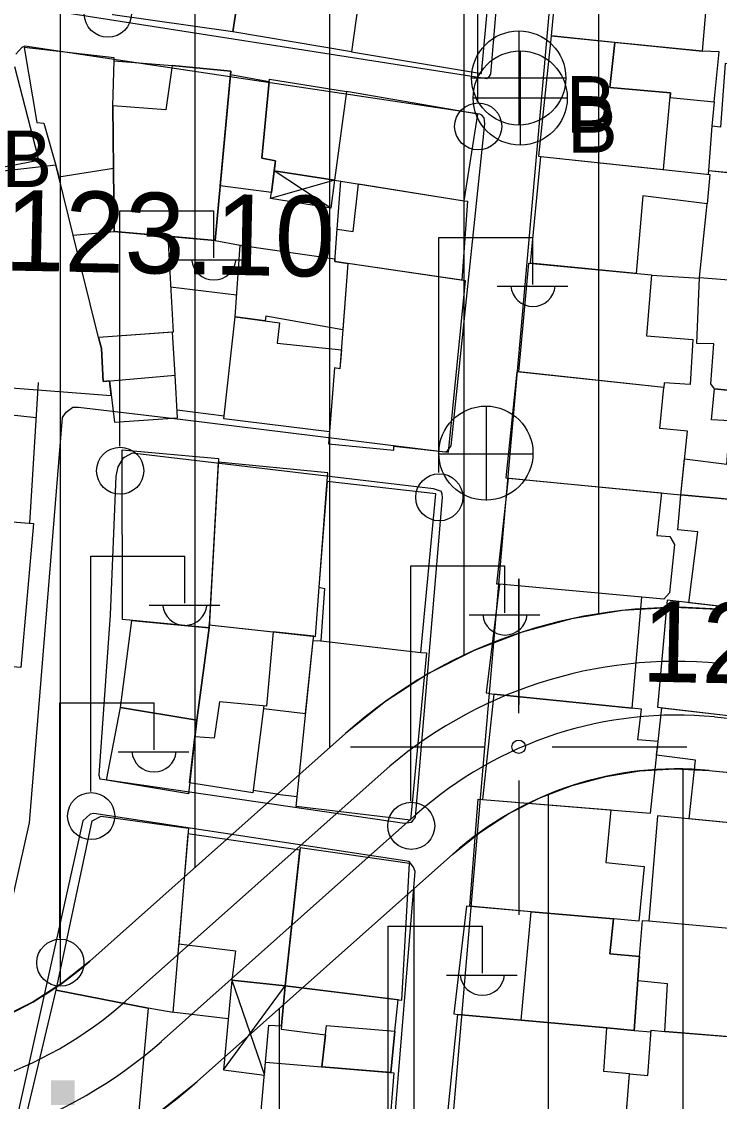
# Model space of a CAD drawing. Extents: x 417997 to 421451, y 4451742 to 4455216.
# Drawn here: x 419463 to 419514.9, y 4452473.6 to 4452553.9 of the extents above; entities that cross this region are included whole.
import ezdxf

# ---------------------------------------------------------------- set-up
doc = ezdxf.new("R2010")
doc.units = 0
for name, color, linetype in [('ADAKENARI', 7, 'Continuous'), ('B_Kapi', 7, 'Continuous'), ('B_Mesken', 7, 'Continuous'), ('B_Sundurma', 7, 'Continuous'), ('B_Teras', 7, 'Continuous'), ('KALDIRIM', 7, 'Continuous'), ('P_Grid', 7, 'Continuous'), ('PAFTALAMA', 7, 'Continuous'), ('PL_KON_MEV_350', 7, 'Continuous'), ('S_Elektrik_Diregi', 7, 'Continuous'), ('S_Rogar_Kapagi', 7, 'Continuous'), ('S_Rogar_Kapagi_Buski', 7, 'Continuous'), ('Sinir_Duvar_tek_tarafa_ait', 7, 'Continuous'), ('TR_ORTAYOGUNKONUT', 7, 'Continuous'), ('Y_Bucak_Koy', 7, 'Continuous'), ('Y_Kot_Noktasi', 7, 'Continuous'), ('Y_Yol_Kotu', 7, 'Continuous'), ('Yol_Sose', 7, 'Continuous')]:
    doc.layers.add(name, color=color, linetype=linetype)

msp = doc.modelspace()

# ---------------------------------------------------------------- linework, layer by layer
at = {"layer": 'ADAKENARI'}
for p, q in [((419487.115, 4452500.985), (419468.114, 4452484.062)), ((419487.115, 4452500.985), (419468.114, 4452484.062)), ((419514.164, 4452498.235), (419572.575, 4452492.506)), ((419514.164, 4452498.235), (419572.575, 4452492.506)), ((419476.095, 4452475.101), (419495.096, 4452492.024)), ((419476.095, 4452475.101), (419495.096, 4452492.024))]:
    msp.add_line(p, q, dxfattribs=at)
for centre, radius, start, end in [((419511.724, 4452473.355), 37, 84.39749, 131.68944), ((419511.724, 4452473.355), 37, 84.39749, 131.68944), ((419511.724, 4452473.355), 25, 84.39749, 131.68944), ((419511.724, 4452473.355), 25, 84.39749, 131.68944), ((419451.487, 4452502.731), 25, 263.99099, 311.68944), ((419451.487, 4452502.731), 25, 263.99099, 311.68944), ((419451.487, 4452502.731), 37, 263.99099, 311.68944), ((419451.487, 4452502.731), 37, 263.99099, 311.68944)]:
    msp.add_arc(centre, radius, start, end, dxfattribs=at)
at = {"layer": 'B_Kapi'}
msp.add_lwpolyline([(419482.052, 4452496.488), (419483.526, 4452496.293)], dxfattribs=at)
at = {"layer": 'B_Mesken'}
for points in [[(419487.577, 4452551.697), (419478.757, 4452553.178), (419480.1, 4452562.035), (419483.31, 4452561.933), (419486.927, 4452561.808), (419487.318, 4452565.246), (419489.412, 4452564.839)], [(419489.412, 4452564.839), (419487.577, 4452551.697), (419497.235, 4452550.077), (419498.082, 4452559.256), (419494.228, 4452559.813), (419494.672, 4452563.733)], [(419478.757, 4452553.178), (419469.823, 4452554.432), (419471.167, 4452563.02), (419476.451, 4452562.322), (419476.543, 4452562.911), (419480.136, 4452562.292), (419480.1, 4452562.035)], [(419502.405, 4452552.868), (419513.663, 4452551.734), (419514.367, 4452559.818), (419503.293, 4452562.166)], [(419510.764, 4452542.939), (419511.283, 4452548.64), (419506.782, 4452549.042), (419507.142, 4452552.391), (419502.405, 4452552.868), (419501.469, 4452543.933), (419501.651, 4452543.909)], [(419469.936, 4452551.01), (419469.937, 4452551.236), (419463.236, 4452552.007), (419464.169, 4452546.436), (419464.712, 4452546.389), (419465.573, 4452543.34), (419465.806, 4452542.4), (419469.875, 4452543.046), (419469.834, 4452547.683)], [(419511.251, 4452548.287), (419514.521, 4452547.981), (419514.896, 4452551.679), (419513.663, 4452551.734), (419507.142, 4452552.391), (419506.782, 4452549.042), (419511.283, 4452548.64)], [(419469.834, 4452547.683), (419469.936, 4452551.01), (419474.25, 4452550.664), (419478.609, 4452550.24), (419477.432, 4452537.646), (419473.92, 4452537.966), (419469.917, 4452538.331), (419469.875, 4452543.046)], [(419526.655, 4452541.789), (419527.383, 4452549.635), (419519.27, 4452550.389), (419515.355, 4452550.832), (419515, 4452546.083), (419514.366, 4452546.153), (419514.106, 4452542.852), (419515.768, 4452542.7), (419519.526, 4452542.357), (419521.054, 4452542.217)], [(419478.587, 4452550.004), (419481.459, 4452549.474), (419480.897, 4452543.779), (419481.914, 4452543.572), (419481.635, 4452541.222), (419477.814, 4452541.728)], [(419481.459, 4452549.474), (419481.482, 4452549.655), (419487.202, 4452548.73), (419486.298, 4452542.155), (419481.827, 4452542.838), (419481.914, 4452543.572), (419480.897, 4452543.779)], [(419486.298, 4452542.155), (419495.952, 4452540.606), (419496.969, 4452547.046), (419487.202, 4452548.73)], [(419500.874, 4452535.959), (419501.651, 4452543.909), (419514.221, 4452542.57), (419514.009, 4452540.39), (419509.236, 4452540.974), (419508.729, 4452535.209)], [(419459.73, 4452542.581), (419457.749, 4452527.056), (419469.704, 4452526.116), (419469.571, 4452527.208), (419469.114, 4452527.167), (419468.979, 4452529.618), (419468.773, 4452530.451), (419466.884, 4452538.059), (419465.806, 4452542.4), (419465.593, 4452543.262)], [(419466.884, 4452538.059), (419465.806, 4452542.4), (419469.875, 4452543.046), (419469.917, 4452538.331), (419473.92, 4452537.966), (419474.304, 4452530.836), (419468.773, 4452530.451)], [(419495.952, 4452540.606), (419496.201, 4452540.583), (419495.785, 4452534.708), (419487.303, 4452535.942), (419486.331, 4452536.104), (419486.498, 4452538.5), (419487.696, 4452538.315), (419488.086, 4452541.868)], [(419478.919, 4452531.972), (419479.299, 4452537.306), (419486.344, 4452536.287), (419486.331, 4452536.104), (419487.303, 4452535.942), (419486.931, 4452531.021), (419481.211, 4452532.036), (419481.163, 4452531.672)], [(419487.303, 4452535.942), (419486.712, 4452528.123), (419486.305, 4452528.192), (419485.856, 4452522.542), (419490.719, 4452522.05), (419490.72, 4452522.366), (419494.79, 4452521.922), (419496.054, 4452534.668)], [(419500.001, 4452527.881), (419500.754, 4452535.971), (419509.869, 4452535.1), (419509.514, 4452530.568), (419512.954, 4452530.292), (419512.739, 4452526.939), (419510.811, 4452527.081), (419510.784, 4452526.727)], [(419525.903, 4452533.648), (419525.196, 4452525.538), (419514.563, 4452526.618), (419514.292, 4452527.004), (419514.506, 4452529.972), (419513.236, 4452529.999), (419513.434, 4452534.893), (419515.313, 4452534.749), (419519.137, 4452534.396)], [(419485.927, 4452523.425), (419478.08, 4452524.402), (419478.919, 4452531.972), (419482.221, 4452531.531), (419482.035, 4452530.017), (419486.819, 4452529.536), (419486.712, 4452528.123), (419486.305, 4452528.192)], [(419474.46, 4452527.646), (419474.263, 4452530.833), (419468.773, 4452530.451), (419468.979, 4452529.618), (419469.114, 4452527.167), (419469.571, 4452527.208), (419469.945, 4452524.151), (419474.634, 4452524.474)], [(419499.037, 4452519.995), (419512.047, 4452518.739), (419512.538, 4452523.464), (419510.502, 4452523.675), (419510.784, 4452526.727), (419499.856, 4452527.897)], [(419525.196, 4452525.538), (419525.468, 4452525.537), (419524.725, 4452517.583), (419512.047, 4452518.739), (419512.326, 4452521.429), (419515.477, 4452521.01), (419515.715, 4452524.249), (419514.332, 4452524.322), (419514.563, 4452526.618)], [(419477.679, 4452521.436), (419476.981, 4452508.848), (419470.559, 4452509.459), (419470.533, 4452522.094)], [(419476.994, 4452509.077), (419484.907, 4452508.212), (419485.172, 4452511.862), (419485.722, 4452519.14), (419485.817, 4452520.383), (419477.664, 4452521.178)], [(419485.301, 4452507.869), (419492.717, 4452507.006), (419493.842, 4452518.824), (419485.77, 4452519.734), (419485.134, 4452511.871), (419485.563, 4452511.779)], [(419498.572, 4452512.086), (419498.369, 4452512.087), (419499.25, 4452519.974), (419510.609, 4452518.878), (419510.259, 4452515.713), (419511.232, 4452515.642), (419511.592, 4452515.053), (419511.218, 4452511.458), (419510.786, 4452510.985), (419509.161, 4452511.121)], [(419512.654, 4452510.71), (419513.328, 4452515.976), (419511.835, 4452516.14), (419512.047, 4452518.739), (419524.942, 4452517.563), (419524.165, 4452509.391)], [(419451.216, 4452504.421), (419452.483, 4452517.505), (419463.944, 4452516.603), (419462.979, 4452505.896), (419459.65, 4452506.18), (419459.412, 4452502.874), (419455.879, 4452503.204), (419455.904, 4452504.065)], [(419508.432, 4452502.869), (419509.161, 4452511.121), (419498.572, 4452512.086), (419497.572, 4452504.016), (419498.15, 4452503.924)], [(419510.317, 4452502.943), (419523.36, 4452501.419), (419524.165, 4452509.391), (419511.041, 4452510.895)], [(419476.981, 4452508.848), (419476.076, 4452501.98), (419470.402, 4452502.927), (419471.236, 4452509.395)], [(419481.055, 4452503.04), (419480.242, 4452496.578), (419475.541, 4452497.313), (419475.933, 4452500.735), (419476.076, 4452501.98), (419476.981, 4452508.848), (419476.994, 4452509.077), (419481.75, 4452508.557), (419481.257, 4452503.021)], [(419481.032, 4452502.852), (419484.158, 4452502.484), (419484.713, 4452507.916), (419484.784, 4452508.226), (419481.75, 4452508.557), (419481.257, 4452503.021), (419481.055, 4452503.04)], [(419492.717, 4452507.006), (419493.147, 4452506.982), (419491.952, 4452494.532), (419483.451, 4452495.557), (419484.713, 4452507.916), (419485.301, 4452507.869)], [(419497.309, 4452496.08), (419509.799, 4452495.062), (419510.36, 4452500.397), (419508.866, 4452500.515), (419509.123, 4452502.798), (419498.15, 4452503.924)], [(419469.366, 4452497.506), (419470.402, 4452502.927), (419476.076, 4452501.98), (419475.447, 4452496.49)], [(419522.878, 4452501.476), (419522.038, 4452493.729), (419512.667, 4452494.639), (419513.135, 4452499.009), (419510.253, 4452499.385), (419510.36, 4452500.397), (419510.648, 4452502.904)], [(419496.367, 4452488.134), (419496.992, 4452496.104), (419497.309, 4452496.08), (419506.843, 4452495.303), (419506.468, 4452491.392), (419509.318, 4452491.087), (419508.943, 4452487.04), (419507.037, 4452487.212), (419500.928, 4452487.732)], [(419465.629, 4452481.899), (419468.297, 4452494.493), (419468.955, 4452494.852), (419475.45, 4452493.946), (419474.295, 4452480.238), (419472.452, 4452480.557)], [(419509.685, 4452487.055), (419521.334, 4452485.996), (419522.038, 4452493.729), (419510.31, 4452494.868)], [(419483.725, 4452492.305), (419475.414, 4452493.516), (419474.726, 4452485.35), (419478.958, 4452484.814), (419478.679, 4452482.643), (419482.646, 4452482.217)], [(419483.744, 4452492.485), (419482.646, 4452482.217), (419491.314, 4452481.144), (419491.891, 4452491.324)], [(419500.928, 4452487.732), (419496.109, 4452488.157), (419495.177, 4452480.132), (419495.44, 4452480.079), (419500.177, 4452479.661), (419506.554, 4452479.1), (419508.594, 4452478.907), (419508.594, 4452478.907), (419508.974, 4452484.401), (419506.78, 4452484.59), (419507.037, 4452487.212)], [(419521.334, 4452485.996), (419521.877, 4452485.949), (419521.149, 4452477.991), (419510.854, 4452478.82), (419511.069, 4452482.37), (419508.849, 4452482.598), (419508.974, 4452484.401), (419509.209, 4452487.069), (419509.685, 4452487.055)], [(419462.653, 4452469.381), (419465.629, 4452481.899), (419472.452, 4452480.557), (419471.333, 4452468.292)], [(419490.784, 4452478.857), (419491.035, 4452481.178), (419482.646, 4452482.217), (419482.341, 4452479.005), (419485.635, 4452478.587), (419485.364, 4452476.207), (419490.498, 4452475.779)], [(419494.656, 4452472.243), (419507.843, 4452470.678), (419508.239, 4452475.683), (419506.323, 4452475.85), (419506.554, 4452479.1), (419495.44, 4452480.079)], [(419520.78, 4452478.02), (419520.634, 4452474.742), (419520.362, 4452474.652), (419519.896, 4452470.004), (419508.848, 4452470.815), (419507.864, 4452470.941), (419508.239, 4452475.683), (419509.596, 4452475.542), (419509.857, 4452478.934), (419510.854, 4452478.82)], [(419480.333, 4452467.101), (419481.183, 4452476.554), (419490.722, 4452475.761), (419489.972, 4452466.427)]]:
    msp.add_lwpolyline(points, close=True, dxfattribs=at)
at = {"layer": 'B_Sundurma'}
for p, q in [((419486.298, 4452542.155), (419481.543, 4452540.77)), ((419486.042, 4452540.053), (419481.827, 4452542.838)), ((419478.679, 4452482.643), (419481.095, 4452475.575)), ((419478.067, 4452475.966), (419482.646, 4452482.217))]:
    msp.add_line(p, q, dxfattribs=at)
for points in [[(419486.298, 4452542.155), (419486.042, 4452540.053), (419481.543, 4452540.77), (419481.635, 4452541.222), (419481.827, 4452542.838)], [(419478.679, 4452482.643), (419478.067, 4452475.966), (419481.095, 4452475.575), (419481.183, 4452476.554), (419481.423, 4452479.294), (419482.363, 4452479.241), (419482.646, 4452482.217)]]:
    msp.add_lwpolyline(points, close=True, dxfattribs=at)
at = {"layer": 'B_Teras'}
for points in [[(419469.834, 4452547.683), (419469.917, 4452538.331), (419477.432, 4452537.646), (419478.609, 4452550.24), (419474.25, 4452550.664), (419473.762, 4452547.374)], [(419514.106, 4452542.852), (419521.054, 4452542.217), (419521.242, 4452544.275), (419518.685, 4452544.532), (419519.27, 4452550.389), (419515.355, 4452550.832), (419515, 4452546.083), (419514.366, 4452546.153)], [(419473.92, 4452537.966), (419474.304, 4452530.836), (419468.773, 4452530.451), (419466.884, 4452538.059), (419469.917, 4452538.331)], [(419469.114, 4452527.167), (419474.46, 4452527.646), (419474.263, 4452530.833), (419468.773, 4452530.451), (419468.979, 4452529.618)], [(419481.75, 4452508.557), (419481.257, 4452503.021), (419477.752, 4452503.35), (419477.359, 4452500.639), (419475.933, 4452500.735), (419476.076, 4452501.98), (419476.981, 4452508.848), (419476.994, 4452509.077)], [(419500.177, 4452479.661), (419500.928, 4452487.732), (419507.037, 4452487.212), (419506.78, 4452484.59), (419508.974, 4452484.401), (419508.594, 4452478.907), (419506.554, 4452479.1)], [(419485.364, 4452476.207), (419485.714, 4452479.282), (419490.784, 4452478.857), (419490.498, 4452475.779)]]:
    msp.add_lwpolyline(points, close=True, dxfattribs=at)
at = {"layer": 'KALDIRIM'}
for p, q in [((419514.555, 4452502.216), (419584.914, 4452495.314)), ((419514.555, 4452502.216), (419584.914, 4452495.314)), ((419489.776, 4452497.998), (419470.775, 4452481.075)), ((419489.776, 4452497.998), (419470.775, 4452481.075)), ((419492.436, 4452495.011), (419473.435, 4452478.088)), ((419492.436, 4452495.011), (419473.435, 4452478.088))]:
    msp.add_line(p, q, dxfattribs=at)
for centre, radius, start, end in [((419511.724, 4452473.355), 33, 84.39749, 131.68944), ((419511.724, 4452473.355), 33, 84.39749, 131.68944), ((419511.724, 4452473.355), 29, 84.39749, 131.68944), ((419511.724, 4452473.355), 29, 84.39749, 131.68944), ((419451.487, 4452502.731), 29, 263.99099, 311.68944), ((419451.487, 4452502.731), 29, 263.99099, 311.68944), ((419451.487, 4452502.731), 33, 263.99099, 311.68944), ((419451.487, 4452502.731), 33, 263.99099, 311.68944)]:
    msp.add_arc(centre, radius, start, end, dxfattribs=at)
at = {"layer": 'P_Grid'}
for p, q in [((419500, 4452512.5), (419500, 4452503.125)), ((419487.5, 4452500), (419496.875, 4452500)), ((419500, 4452500), (419500, 4452500)), ((419503.125, 4452500), (419512.5, 4452500)), ((419500, 4452496.875), (419500, 4452487.5))]:
    msp.add_line(p, q, dxfattribs=at)
at = {"layer": 'PAFTALAMA'}
for p, q in [((419500, 4452502.5), (419500, 4452512.5)), ((419500, 4452502.5), (419500, 4452512.5)), ((419487.5, 4452500), (419497.5, 4452500)), ((419487.5, 4452500), (419497.5, 4452500)), ((419502.5, 4452500), (419512.5, 4452500)), ((419502.5, 4452500), (419512.5, 4452500)), ((419500, 4452497.5), (419500, 4452487.5)), ((419500, 4452497.5), (419500, 4452487.5))]:
    msp.add_line(p, q, dxfattribs=at)
msp.add_circle((419500, 4452500), 0.5, dxfattribs=at)
msp.add_circle((419500, 4452500), 0.5, dxfattribs=at)
at = {"layer": 'PL_KON_MEV_350'}
for points in [[(419623.77, 4452499.541), (419582.687, 4452503.571), (419582.069, 4452520.257), (419530.931, 4452527.141), (419524.438, 4452509.285), (419515.336, 4452510.178), (419511.524, 4452510.354), (419507.714, 4452510.137), (419503.948, 4452509.528), (419500.263, 4452508.535), (419496.701, 4452507.168), (419493.298, 4452505.441), (419490.092, 4452503.373), (419487.115, 4452500.985), (419468.114, 4452484.062), (419466.085, 4452482.436), (419463.898, 4452481.029), (419461.577, 4452479.858)], [(419462.822, 4452467.51), (419466.42, 4452468.878), (419469.855, 4452470.612), (419473.092, 4452472.694), (419476.095, 4452475.101), (419495.096, 4452492.024), (419497.107, 4452493.637), (419499.274, 4452495.035), (419501.573, 4452496.201), (419503.98, 4452497.125), (419506.469, 4452497.797), (419509.015, 4452498.208), (419511.589, 4452498.354), (419514.164, 4452498.235), (419572.575, 4452492.506), (419567.658, 4452443.954), (419562.661, 4452394.609)]]:
    msp.add_lwpolyline(points, dxfattribs=at)
at = {"layer": 'S_Elektrik_Diregi'}
for p, q in [((419496.954, 4452547.973), (419496.954, 4452565.473)), ((419470.338, 4452522.366), (419470.338, 4452539.867)), ((419470.338, 4452539.867), (419477.338, 4452539.867)), ((419477.338, 4452536.367), (419477.338, 4452539.867)), ((419494.062, 4452520.391), (419494.062, 4452537.891)), ((419494.062, 4452537.891), (419501.062, 4452537.891)), ((419501.062, 4452534.391), (419501.062, 4452537.891)), ((419474.678, 4452536.227), (419479.928, 4452536.227)), ((419498.402, 4452534.251), (419503.652, 4452534.251)), ((419468.182, 4452496.678), (419468.182, 4452514.178)), ((419468.182, 4452514.178), (419475.182, 4452514.178)), ((419475.182, 4452510.678), (419475.182, 4452514.178)), ((419491.979, 4452495.956), (419491.979, 4452513.456)), ((419491.979, 4452513.456), (419498.979, 4452513.456)), ((419498.979, 4452509.956), (419498.979, 4452513.456)), ((419472.522, 4452510.538), (419477.772, 4452510.538)), ((419496.319, 4452509.816), (419501.569, 4452509.816)), ((419465.892, 4452485.776), (419465.892, 4452503.276)), ((419465.892, 4452503.276), (419472.892, 4452503.276)), ((419472.892, 4452499.776), (419472.892, 4452503.276)), ((419470.232, 4452499.636), (419475.482, 4452499.636)), ((419490.298, 4452469.163), (419490.298, 4452486.663)), ((419490.298, 4452486.663), (419497.298, 4452486.663)), ((419497.298, 4452483.163), (419497.298, 4452486.663)), ((419494.638, 4452483.023), (419499.888, 4452483.023))]:
    msp.add_line(p, q, dxfattribs=at)
for centre in [(419469.459, 4452554.517), (419496.99, 4452546.137), (419470.374, 4452520.531), (419494.098, 4452518.555), (419468.218, 4452494.843), (419492.015, 4452494.121), (419465.928, 4452483.941)]:
    msp.add_circle(centre, 1.75, dxfattribs=at)
for centre in [(419477.339, 4452536.379), (419501.063, 4452534.404), (419475.183, 4452510.691), (419498.98, 4452509.969), (419472.893, 4452499.789), (419497.299, 4452483.176)]:
    msp.add_arc(centre, 1.658, 184.83843, 355.14641, dxfattribs=at)
at = {"layer": 'S_Rogar_Kapagi'}
for p, q in [((419497.615, 4452518.315), (419497.615, 4452525.315)), ((419494.045, 4452521.78), (419501.045, 4452521.78))]:
    msp.add_line(p, q, dxfattribs=at)
msp.add_circle((419497.562, 4452521.843), 3.5, dxfattribs=at)
at = {"layer": 'S_Rogar_Kapagi_Buski'}
for p, q in [((419500.003, 4452553.246), (419500.003, 4452546.246)), ((419500.113, 4452551.756), (419500.113, 4452544.756)), ((419496.503, 4452549.746), (419503.503, 4452549.746)), ((419496.613, 4452548.256), (419503.613, 4452548.256))]:
    msp.add_line(p, q, dxfattribs=at)
for centre in [(419500.003, 4452549.746), (419500.113, 4452548.256)]:
    msp.add_circle(centre, 3.5, dxfattribs=at)
at = {"layer": 'Sinir_Duvar_tek_tarafa_ait'}
for points in [[(419514.521, 4452547.981), (419514.366, 4452546.153)], [(419486.498, 4452538.5), (419486.789, 4452542.076)], [(419514.106, 4452542.852), (419514.078, 4452542.586)], [(419513.434, 4452534.893), (419514.009, 4452540.39)], [(419477.432, 4452537.646), (419479.299, 4452537.306)], [(419509.868, 4452535.085), (419513.432, 4452534.851)], [(419479.034, 4452533.587), (419474.124, 4452534.181)], [(419464.278, 4452527.098), (419463.638, 4452516.627)], [(419450.817, 4452525.463), (419450.842, 4452525.917), (419464.119, 4452524.485)], [(419478.102, 4452524.601), (419474.603, 4452525.043)], [(419482.052, 4452496.488), (419480.264, 4452496.757)], [(419478.414, 4452479.755), (419474.226, 4452480.25)], [(419508.594, 4452478.907), (419509.846, 4452478.802)]]:
    msp.add_lwpolyline(points, dxfattribs=at)
at = {"layer": 'TR_ORTAYOGUNKONUT'}
for p, q in [((419505.951, 4452509.852), (419505.951, 4452585.858)), ((419505.951, 4452509.852), (419505.951, 4452585.858)), ((419495.951, 4452506.787), (419495.951, 4452583.292)), ((419495.951, 4452506.787), (419495.951, 4452583.292)), ((419485.951, 4452499.948), (419485.951, 4452580.726)), ((419485.951, 4452499.948), (419485.951, 4452580.726)), ((419475.951, 4452491.042), (419475.951, 4452578.16)), ((419475.951, 4452491.042), (419475.951, 4452578.16)), ((419465.951, 4452482.35), (419465.951, 4452575.594)), ((419465.951, 4452482.35), (419465.951, 4452575.594)), ((419512.22, 4452469.372), (419512.22, 4452498.325)), ((419512.22, 4452469.372), (419512.22, 4452498.325)), ((419502.22, 4452470.783), (419502.22, 4452496.45)), ((419502.22, 4452470.783), (419502.22, 4452496.45)), ((419492.22, 4452467.991), (419492.22, 4452489.462)), ((419492.22, 4452467.991), (419492.22, 4452489.462)), ((419482.22, 4452458.459), (419482.22, 4452480.556)), ((419482.22, 4452458.459), (419482.22, 4452480.556))]:
    msp.add_line(p, q, dxfattribs=at)
at = {"layer": 'Yol_Sose'}
for points in [[(419454.819, 4452572.288), (419470.635, 4452575.603), (419471.525, 4452575.714), (419496.708, 4452575.903), (419497.186, 4452575.651), (419497.345, 4452575.514), (419497.526, 4452575.172), (419498.994, 4452564.189), (419498.943, 4452562.412), (419497.898, 4452550.027), (419497.715, 4452549.732), (419497.624, 4452549.687), (419462.778, 4452555.128)], [(419528.036, 4452554.843), (419527.871, 4452553.181), (419522.637, 4452494.342), (419518.926, 4452447.707), (419517.705, 4452436.869), (419517.361, 4452436.323), (419516.448, 4452436.03), (419492.746, 4452438.405), (419492.428, 4452438.633), (419492.11, 4452439.067), (419492.021, 4452439.682), (419494.07, 4452460.21), (419494.237, 4452462.019), (419499.017, 4452517.864), (419503.321, 4452566.529)], [(419457.188, 4452465.658), (419463.629, 4452494.347), (419466.095, 4452524.502), (419466.369, 4452524.887), (419466.848, 4452525.272), (419467.28, 4452525.27), (419475.036, 4452524.342), (419494.502, 4452521.932), (419494.684, 4452521.999), (419494.981, 4452522.385), (419497.495, 4452546.339), (419497.428, 4452546.771), (419497.269, 4452546.976), (419497.11, 4452547.045), (419463.299, 4452552.098), (419463.071, 4452552.008), (419462.614, 4452551.509)], [(419462.52, 4452550.6), (419464.25, 4452543.887), (419464.181, 4452543.637), (419464.18, 4452543.592), (419431.901, 4452537.386)]]:
    msp.add_lwpolyline(points, dxfattribs=at)
for points in [[(419469.418, 4452497.554), (419491.509, 4452494.315), (419492.009, 4452494.404), (419492.1, 4452494.472), (419492.329, 4452494.767), (419494.34, 4452518.529), (419494.319, 4452518.779), (419494.274, 4452518.961), (419494.251, 4452518.984), (419493.661, 4452519.19), (419471.272, 4452521.84), (419470.68, 4452521.524), (419470.566, 4452521.433), (419470.2, 4452520.821), (419470.062, 4452520.117), (419469.641, 4452509.802), (419468.783, 4452497.897), (419468.873, 4452497.624)], [(419462.998, 4452468.551), (419488.224, 4452466.21), (419489.2, 4452466.161), (419489.518, 4452466.182), (419489.813, 4452466.204), (419490.086, 4452466.316), (419490.178, 4452466.43), (419490.338, 4452466.883), (419492.302, 4452490.732), (419492.19, 4452491.051), (419491.851, 4452491.461), (419468.423, 4452495.044), (419468.151, 4452494.977), (419467.604, 4452494.502), (419462.024, 4452469.372), (419462.113, 4452468.804), (419462.339, 4452468.531)]]:
    msp.add_lwpolyline(points, close=True, dxfattribs=at)

# ---------------------------------------------------------------- texts
at = {"layer": 'S_Rogar_Kapagi_Buski'}
for p in [(419503.503, 4452545.681), (419503.613, 4452544.191), (419461.563, 4452541.631)]:
    msp.add_text('B', height=4.2, dxfattribs=at).set_placement(p)
at = {"layer": 'Y_Bucak_Koy'}
msp.add_text('Santral Garaj Mahallesi', height=15, dxfattribs=at).set_placement((419259.877, 4452459.385))
at = {"layer": 'Y_Kot_Noktasi'}
msp.add_text('123.10 ', height=6, rotation=358.87031, dxfattribs=at).set_placement((419461.744, 4452535.431))
at = {"layer": 'Y_Yol_Kotu'}
msp.add_text('123.71 ', height=6, rotation=358.87031, dxfattribs=at).set_placement((419509.093, 4452504.854))

doc.saveas('drawing.dxf')
